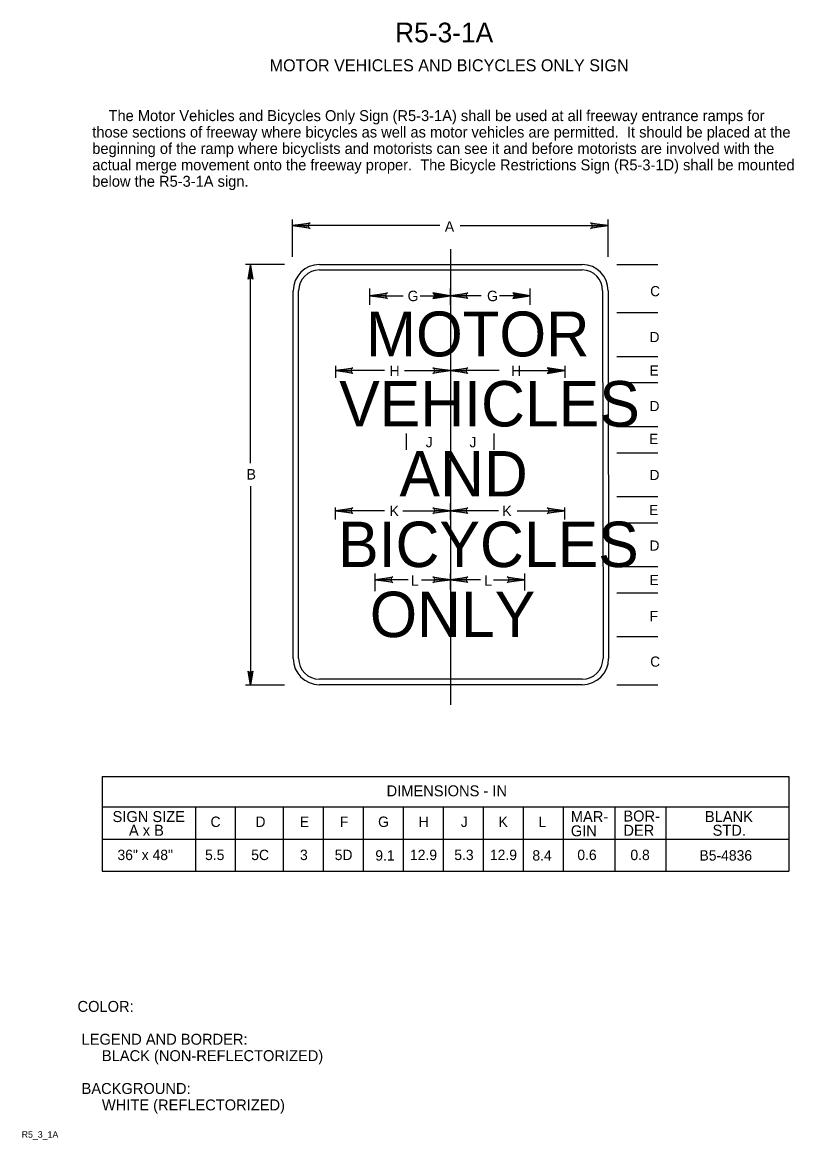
# Model space of a CAD drawing. Extents: x 0.013 to 0.189, y 0.004 to 0.259.
import ezdxf

# ---------------------------------------------------------------- set-up
doc = ezdxf.new("R2010")
doc.units = 0
for name, color, linetype in [('1', 7, 'Continuous'), ('11', 7, 'Continuous'), ('12', 7, 'Continuous'), ('2', 7, 'Continuous'), ('3', 7, 'Continuous')]:
    doc.layers.add(name, color=color, linetype=linetype)

# ---------------------------------------------------------------- blocks, each defined once
blk = doc.blocks.new('RARROW')
at = {"layer": '3'}
for p, q in [((-2.156, 0.285), (-2.2665, 0.384625)), ((-2.2665, 0.384625), (0, 0)), ((0, 0), (-2.2665, -0.379125)), ((-2.156, 0.285), (-2.075625, 0.12075)), ((0, 0), (-2.156, 0.285)), ((-2.14975, -0.2705), (0, 0)), ((-2.075625, 0.12075), (0, 0)), ((0, 0), (-2.074, -0.108)), ((-2.2665, -0.379125), (-2.14975, -0.2705)), ((-2.074, -0.108), (-2.14975, -0.2705))]:
    blk.add_line(p, q, dxfattribs=at)

msp = doc.modelspace()

# ---------------------------------------------------------------- linework, layer by layer
at = {"layer": '11'}
for p, q in [((0.08037, 0.20388), (0.14037, 0.20388)), ((0.14037, 0.20388), (0.14037, 0.20388)), ((0.07437, 0.11387), (0.07437, 0.19787)), ((0.14625, 0.19787), (0.14638, 0.11387)), ((0.14037, 0.10787), (0.08037, 0.10787))]:
    msp.add_line(p, q, dxfattribs=at)
for centre, radius, start, end in [((0.08037, 0.19787), 0.006, 90, 180), ((0.14031, 0.19794), 0.00594, 359.3969, 89.3969), ((0.08037, 0.11387), 0.006, 180, 270), ((0.14037, 0.11387), 0.006, 270, 0)]:
    msp.add_arc(centre, radius, start, end, dxfattribs=at)
at = {"layer": '3'}
for p, q in [((0.07425, 0.20563), (0.07425, 0.21413)), ((0.10787, 0.21275), (0.07425, 0.21275)), ((0.1125, 0.21275), (0.14625, 0.21275)), ((0.14625, 0.20563), (0.14625, 0.21413)), ((0.11025, 0.20738), (0.11025, 0.10325)), ((0.07237, 0.20388), (0.0635, 0.20388)), ((0.06463, 0.1585), (0.06463, 0.20388)), ((0.08037, 0.20262), (0.14037, 0.20262)), ((0.14825, 0.20388), (0.15763, 0.20388)), ((0.07562, 0.11387), (0.07562, 0.19787)), ((0.09187, 0.19462), (0.09187, 0.19837)), ((0.09187, 0.19675), (0.0995, 0.19675)), ((0.10338, 0.19675), (0.11025, 0.19675)), ((0.11025, 0.19462), (0.11025, 0.19837)), ((0.11725, 0.19675), (0.11025, 0.19675)), ((0.1285, 0.19675), (0.1215, 0.19675)), ((0.1285, 0.19462), (0.1285, 0.19837)), ((0.145, 0.19787), (0.14513, 0.11387)), ((0.14825, 0.19287), (0.15763, 0.19287)), ((0.14825, 0.18288), (0.15763, 0.18288)), ((0.084, 0.18075), (0.084, 0.178)), ((0.09525, 0.17963), (0.084, 0.17963)), ((0.09975, 0.17963), (0.11025, 0.17963)), ((0.11025, 0.18075), (0.11025, 0.178)), ((0.12137, 0.17963), (0.11025, 0.17963)), ((0.1255, 0.17963), (0.13637, 0.17963)), ((0.13637, 0.18075), (0.13637, 0.178)), ((0.14825, 0.17688), (0.15763, 0.17688)), ((0.14825, 0.16687), (0.15763, 0.16687)), ((0.10025, 0.1615), (0.10025, 0.16525)), ((0.12025, 0.1615), (0.12025, 0.16525)), ((0.14825, 0.16087), (0.15763, 0.16087)), ((0.06463, 0.15325), (0.06463, 0.10787)), ((0.14825, 0.15088), (0.15763, 0.15088)), ((0.084, 0.14563), (0.084, 0.14838)), ((0.11025, 0.14563), (0.11025, 0.14925)), ((0.13637, 0.14563), (0.13637, 0.14838)), ((0.09525, 0.14763), (0.084, 0.14763)), ((0.09938, 0.14763), (0.11025, 0.14763)), ((0.12125, 0.14763), (0.11025, 0.14763)), ((0.1255, 0.14763), (0.13637, 0.14763)), ((0.14825, 0.14488), (0.15763, 0.14488)), ((0.09312, 0.12925), (0.09312, 0.13325)), ((0.11025, 0.12962), (0.11025, 0.13325)), ((0.12725, 0.12937), (0.12725, 0.13325)), ((0.14825, 0.13487), (0.15763, 0.13487)), ((0.10063, 0.13187), (0.09312, 0.13187)), ((0.10363, 0.13187), (0.11025, 0.13187)), ((0.11713, 0.13187), (0.11025, 0.13187)), ((0.12012, 0.13187), (0.12725, 0.13187)), ((0.14825, 0.12887), (0.15763, 0.12887)), ((0.14825, 0.11888), (0.15763, 0.11888)), ((0.07237, 0.10775), (0.0635, 0.10775)), ((0.14037, 0.10912), (0.08037, 0.10912)), ((0.14825, 0.10787), (0.15763, 0.10787)), ((0.03075, 0.08688), (0.1875, 0.08688)), ((0.03075, 0.08688), (0.03075, 0.06525)), ((0.1875, 0.08688), (0.1875, 0.06525)), ((0.03075, 0.08), (0.1875, 0.08)), ((0.05204, 0.08), (0.05204, 0.06525)), ((0.06112, 0.08), (0.06112, 0.06525)), ((0.07212, 0.08), (0.07212, 0.06525)), ((0.08125, 0.08), (0.08125, 0.06525)), ((0.09037, 0.08), (0.09037, 0.06525)), ((0.0995, 0.08), (0.0995, 0.06525)), ((0.10862, 0.08), (0.10862, 0.06525)), ((0.11775, 0.08), (0.11775, 0.06525)), ((0.12688, 0.08), (0.12688, 0.06525)), ((0.13604, 0.08), (0.13604, 0.06525)), ((0.14779, 0.08), (0.14779, 0.06525)), ((0.15942, 0.08), (0.15942, 0.06525)), ((0.03075, 0.07262), (0.1875, 0.07262)), ((0.03075, 0.06525), (0.1875, 0.06525))]:
    msp.add_line(p, q, dxfattribs=at)
for centre, radius, start, end in [((0.08037, 0.19787), 0.00475, 90, 180), ((0.14031, 0.19794), 0.00469, 359.2361, 89.2361), ((0.08037, 0.11387), 0.00475, 180, 270), ((0.14037, 0.11387), 0.00475, 270, 0)]:
    msp.add_arc(centre, radius, start, end, dxfattribs=at)

# ---------------------------------------------------------------- block references
for p, xscale, yscale, rotation in [((0.07425, 0.21275), 0.0017647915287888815, 0.0017457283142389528, 180), ((0.06463, 0.20375), 0.0014118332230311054, 0.0013965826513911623, 90), ((0.09187, 0.19675), 0.0017647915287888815, 0.0017457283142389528, 180), ((0.11025, 0.19675), 0.0017647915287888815, 0.0017457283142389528, 180), ((0.084, 0.17963), 0.0017647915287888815, 0.0017457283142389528, 180), ((0.11025, 0.17963), 0.0017647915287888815, 0.0017457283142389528, 180), ((0.084, 0.14763), 0.0017647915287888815, 0.0017457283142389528, 180), ((0.11025, 0.14763), 0.0017647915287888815, 0.0017457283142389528, 180), ((0.09312, 0.13187), 0.0017647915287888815, 0.0017457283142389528, 180), ((0.11025, 0.13187), 0.0017647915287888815, 0.0017457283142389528, 180), ((0.06463, 0.10775), 0.0014118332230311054, 0.0013965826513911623, -90)]:
    msp.add_blockref('RARROW', p, dxfattribs=dict(at, xscale=xscale, yscale=yscale, rotation=rotation))
at = {"layer": '3', "xscale": 0.0017647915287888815}
for p, yscale in [((0.14625, 0.21275), 0.0017457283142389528), ((0.11025, 0.19675), -0.0017457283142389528), ((0.1285, 0.19675), -0.0017457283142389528), ((0.11025, 0.17963), 0.0017457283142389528), ((0.13637, 0.17963), -0.0017457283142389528), ((0.11025, 0.14763), 0.0017457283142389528), ((0.13637, 0.14763), 0.0017457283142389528), ((0.11025, 0.13187), 0.0017457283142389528), ((0.12725, 0.13187), 0.0017457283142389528)]:
    msp.add_blockref('RARROW', p, dxfattribs=dict(at, yscale=yscale))

# ---------------------------------------------------------------- texts
at = {"layer": '1'}
for s, height, p in [('R5-3-1A', 0.0045, (0.09763, 0.25462)), ('MOTOR VEHICLES AND BICYCLES ONLY SIGN', 0.0027503, (0.069, 0.248)), ('COLOR:', 0.0025, (0.02513, 0.03313)), (' LEGEND AND BORDER:', 0.0024998, (0.02513, 0.02563)), ('      BLACK (NON-REFLECTORIZED)', 0.0024998, (0.02513, 0.02188)), (' BACKGROUND:', 0.0024998, (0.02513, 0.01438)), ('      WHITE (REFLECTORIZED)', 0.0024998, (0.02513, 0.01063)), ('R5_3_1A', 0.0015, (0.01238, 0.00438))]:
    msp.add_text(s, height=height, dxfattribs=at).set_placement(p)
at = {"layer": '12'}
for s, height, p in [('MOTOR', 0.01025, (0.091, 0.18288)), ('VEHICLES', 0.010375, (0.08488, 0.16687)), ('AND', 0.010375, (0.09863, 0.15088)), ('BICYCLES', 0.010375, (0.08463, 0.13475)), ('ONLY', 0.010375, (0.09187, 0.11875))]:
    msp.add_text(s, height=height, dxfattribs=at).set_placement(p)
at = {"layer": '2'}
for s, height, p in [('    The Motor Vehicles and Bicycles Only Sign (R5-3-1A) shall be used at all freeway entrance ramps for', 0.00249975, (0.0285, 0.23663)), ('those sections of freeway where bicycles as well as motor vehicles are permitted.  It should be placed at the', 0.00249975, (0.0285, 0.23288)), ('beginning of the ramp where bicyclists and motorists can see it and before motorists are involved with the', 0.00249975, (0.0285, 0.22913)), ('actual merge movement onto the freeway proper.  The Bicycle Restrictions Sign (R5-3-1D) shall be mounted', 0.00249975, (0.0285, 0.22538)), ('below the R5-3-1A sign.', 0.0024998, (0.0285, 0.22163))]:
    msp.add_text(s, height=height, dxfattribs=at).set_placement(p)
at = {"layer": '3'}
for s, height, p in [('A', 0.00237, (0.109, 0.21138)), ('G', 0.00238, (0.1005, 0.1955)), ('G', 0.00238, (0.11863, 0.1955)), ('C', 0.00232, (0.15588, 0.19662)), ('D', 0.00232, (0.15575, 0.18613)), ('H', 0.00237, (0.09638, 0.17838)), ('H', 0.00237, (0.12412, 0.17838)), ('E', 0.00232, (0.15575, 0.1785)), ('D', 0.00232, (0.15575, 0.17037)), ('J', 0.00237, (0.10462, 0.16212)), ('J', 0.00237, (0.11463, 0.16212)), ('E', 0.00232, (0.15563, 0.16287)), ('B', 0.00238, (0.06375, 0.15475)), ('D', 0.00232, (0.15575, 0.15463)), ('K', 0.00238, (0.09638, 0.14638)), ('K', 0.00238, (0.12212, 0.14638)), ('E', 0.00232, (0.15563, 0.14663)), ('D', 0.00232, (0.15575, 0.1385)), ('L', 0.00238, (0.10125, 0.1305)), ('L', 0.00238, (0.118, 0.1305)), ('E', 0.00232, (0.15575, 0.13062)), ('F', 0.00238, (0.15575, 0.12237)), ('C', 0.00232, (0.15588, 0.112)), ('DIMENSIONS - IN', 0.0024998, (0.0957, 0.08238)), ('BOR-', 0.0025, (0.14975, 0.07662)), ('SIGN SIZE', 0.0025, (0.03313, 0.0765)), ('C', 0.00238, (0.0555, 0.07537)), ('D', 0.00238, (0.06575, 0.07537)), ('E', 0.00238, (0.07587, 0.07537)), ('F', 0.00238, (0.085, 0.07537)), ('G', 0.00238, (0.09375, 0.07537)), ('H', 0.00238, (0.103, 0.07537)), ('J', 0.00238, (0.11263, 0.07537)), ('K', 0.00238, (0.12125, 0.07537)), ('L', 0.00238, (0.13037, 0.07537)), ('MAR-', 0.0025, (0.13775, 0.0765)), ('BLANK', 0.0025, (0.16837, 0.0765)), ('A x B', 0.0025, (0.03687, 0.07337)), ('GIN', 0.0025, (0.13775, 0.07325)), ('DER', 0.0025, (0.14975, 0.07337)), ('STD.', 0.0025, (0.17012, 0.07337)), ('36" x 48"', 0.002375, (0.03425, 0.06781)), ('5.5', 0.002375, (0.05425, 0.06781)), ('5C', 0.002375, (0.06479, 0.06781)), ('3', 0.00238, (0.07593, 0.06781)), ('5D', 0.002375, (0.08385, 0.06781)), ('9.1', 0.002375, (0.09312, 0.06769)), ('12.9', 0.002375, (0.10103, 0.06781)), ('5.3', 0.002375, (0.11115, 0.06781)), ('12.9', 0.002375, (0.11928, 0.06781)), ('8.4', 0.002375, (0.12898, 0.06769)), ('0.6', 0.002375, (0.13924, 0.06781)), ('0.8', 0.002375, (0.15136, 0.06781)), ('B5-4836', 0.002375, (0.16713, 0.06769))]:
    msp.add_text(s, height=height, dxfattribs=at).set_placement(p)

doc.saveas('drawing.dxf')
